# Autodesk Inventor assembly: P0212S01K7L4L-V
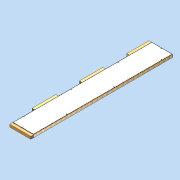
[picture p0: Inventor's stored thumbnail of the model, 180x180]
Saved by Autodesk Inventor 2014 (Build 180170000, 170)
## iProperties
Created: 2011-09
Part Number: P0212S01K7L4L-V
Document SubType Name: Assembly
Designer: david.appleford
Description: 0.5w x 3w 01 Panel - 8 Locks 4 Lugs LH
Mass: 38000 g
Surface Area: 52285.1 cm^2
Volume: 165537 cm^3
Density: 0.229556 g/cm^3
Cost Center: £149.00
Justset: False
Title: 0.5w x 3w 01 Panel - 8 Locks 4 Lugs LH
Author: david.appleford
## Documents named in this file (5)
- C:\Documents and Settings\john.everitt\Local Settings\My Documents\Vault\Production MkII\VIRTUAL ELEMENTS\Virtual Walls\Virtual Timber + MgO\P0212S01K8L4L-V.iam
- C:\Documents and Settings\john.everitt\Local Settings\My Documents\Vault\Production MkII\VIRTUAL ELEMENTS\Virtual Lugs\Superceded Lugs\LA02C3V.ipt
- C:\Documents and Settings\john.everitt\Local Settings\My Documents\Vault\Production MkII\VIRTUAL ELEMENTS\Virtual Lugs\Superceded Lugs\LA02M3V.ipt
- C:\Documents and Settings\john.everitt\Local Settings\My Documents\Vault\Production MkII\VIRTUAL ELEMENTS\Virtual Lugs\Superceded Lugs\LA02E3V.ipt
- C:\Documents and Settings\john.everitt\Local Settings\My Documents\Vault\Production MkII\VIRTUAL ELEMENTS\Virtual Walls\Virtual Timber + MgO\P0212S01K8-V.ipt
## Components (5 placed, 4 different names)
1. P0212S01K8-V:1 — Mate:2, Flush:3, Flush:4, Mate:3, Flush:5, Flush:6, Mate:5, Mate:6, Flush:9, Flush:10
2. LA02E3:1 — Mate:2, Flush:3, Flush:4
3. LA02C3:4 — Mate:3, Flush:5, Flush:6, Mate:11
4. LA02M3:1 — Mate:6, Flush:9, Mate:11, Mate:12
5. LA02M3:2 — Mate:5, Flush:10, Mate:12
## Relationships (12: Mate 6, Flush 6)
- Mate:2: P0212S01K8-V:1 ↔ LA02E3:1
- Flush:3: P0212S01K8-V:1 ↔ LA02E3:1
- Flush:4: P0212S01K8-V:1 ↔ LA02E3:1
- Mate:3: P0212S01K8-V:1 ↔ LA02C3:4
- Flush:5: P0212S01K8-V:1 ↔ LA02C3:4
- Flush:6: P0212S01K8-V:1 ↔ LA02C3:4
- Mate:5: P0212S01K8-V:1 ↔ LA02M3:2
- Mate:6: P0212S01K8-V:1 ↔ LA02M3:1
- Flush:9: P0212S01K8-V:1 ↔ LA02M3:1
- Flush:10: P0212S01K8-V:1 ↔ LA02M3:2
- Mate:11: LA02C3:4 ↔ LA02M3:1
- Mate:12: LA02M3:1 ↔ LA02M3:2
## Named parameters: t = 1 mm, Cl = 2 mm
